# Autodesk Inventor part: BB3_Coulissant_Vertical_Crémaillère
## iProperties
Created: 2009-02
Part Number: BB3_Coulissant_Vertical_Crémaillère
Document SubType Name: Modeling
Designer: Alex_Cyril
Author: Alex_Cyril
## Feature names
1. Extrusion1
